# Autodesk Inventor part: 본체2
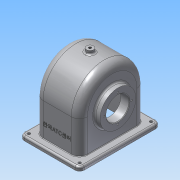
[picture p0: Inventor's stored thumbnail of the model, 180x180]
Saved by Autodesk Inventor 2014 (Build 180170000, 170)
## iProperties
Created: 2016-01
Part Number: 본체2
Material: 알루미늄 6061
Document SubType Name: Modeling
Designer: User
Mass: 842.835 g
Surface Area: 990.698 cm^2
Volume: 311.009 cm^3
Density: 2.71 g/cm^3
Appearance: 알루미늄 - 평지
Author: User
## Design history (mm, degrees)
sketch "스케치1"
  geometry: L1 (-57, 0)-(57, 0); L2 (57, 0)-(57, -64); L3 (57, -64)-(-57, -64); L4 (-57, -64)-(-57, 0); C1 r 57 at (0, 0); 2 further points
  constraints: 8 end point, 2 coincident, 2 parallel, 1 centre point, 1 horizontal, 1 midpoint, 1 perpendicular
  dimensions: "d0" = 114 diameter of C1; "d1" = 114 distance of L2.end L3.end; "d2" = 64 distance of L1.end L2.end
extrude "돌출1" new body sketch "스케치1" stored distance "d3" = 77; taper "d4" = 0 deg
feature "쉘1" dims "d7" = 6
sketch "스케치3"
  geometry: L1 (114, 0)-(114, -77) reference; L2 (0, 0)-(114, 0) reference; L3 (0, 0)-(0, -77) reference; L4 (114, -77)-(0, -77) reference; L5 (-13, 13.5)-(127, 13.5); L6 (127, 13.5)-(127, -90.5); L7 (127, -90.5)-(-13, -90.5); L8 (-13, -90.5)-(-13, 13.5); 3 further points
  constraints: 8 end point, 2 midpoint, 2 parallel, 1 horizontal, 1 horizontal alignment, 1 perpendicular, 1 vertical alignment
  dimensions: "d8" = 140 distance of L5.start L5.end; "d9" = 104 distance of L5.end L6.end
extrude "돌출2" join sketch "스케치3" distance "d10" = 7; taper "d11" = 0 deg
fillet "모깎기1" dims "d12" = 14
node "작업 평면1"
sketch "스케치6"
  geometry: C1 r 6 at (0, 0); 1 further point
  constraints: 1 centre point, 1 coincident
  dimensions: "d36" = 12 diameter of C1
extrude "돌출4" join sketch "스케치6" stored distance "d37" = 10; taper "d38" = 0 deg
hole "구멍2" diameter "d41" = 4.459; stored, may be unused: countersink angle "d45" = 90 deg, drill point angle "d47" = 118 deg; dims "d39" = 10, "d40" = 10, "d42" = 6, "d43" = 4, "d44" = 2, "d46" = 63
fillet "모깎기4" dims "d77" = 8
sketch "스케치9"
  geometry: A1 r 8 centre (119, 82.5) between (127, 82.5) and (119, 90.5) reference; A2 r 8 centre (-5, 82.5) between (-5, 90.5) and (-13, 82.5) reference; A3 r 8 centre (-5, -5.5) between (-13, -5.5) and (-5, -13.5) reference; A4 r 8 centre (119, -5.5) between (119, -13.5) and (127, -5.5) reference; 1 further point
hole "구멍5" sketch "스케치9" at (119, 82.5), (-5, 82.5), (119, -5.5), (-5, -5.5) diameter "d78" = 5; stored, may be unused: countersink angle "d82" = 90 deg, drill point angle "d84" = 118 deg; dims "d79" = 7, "d80" = 4, "d81" = 2, "d83" = 9
fillet "모깎기5" dims "d85" = 3
sketch "스케치10"
  geometry: L1 (49, 0)-(49, -57) reference; L2 (0, 0)-(49, 0) reference; L3 (0, -57)-(0, 0) reference; L4 (-1.387, -30.398)-(50.387, -30.398); L5 (50.387, -30.398)-(50.387, -37.602); L6 (50.387, -37.602)-(-1.387, -37.602); L7 (-1.387, -37.602)-(-1.387, -30.398); L8 (0, -34)-(49, -34); L9 (-19.5, -64)-(68.5, -64) reference; L10 (24.5, 0)-(24.5, -54); L11 (-14, 0)-(-14, -57) reference; L12 (68.5, -57)-(-19.5, -57) reference; 4 further points
  constraints: 4 end point, 4 midpoint, 2 point on line, 1 horizontal alignment, 1 perpendicular, 1 vertical alignment, 2 other
  dimensions: "d86" = 30 distance between parallel lines of L9 L8; "d87" = 38.5 distance between parallel lines of L11 L10
feature "엠보싱1" sketch "스케치10" dims "d8" = 140, "d9" = 104, "d88" = 0.5, "d89" = 0
sketch "스케치11"
  geometry: L1 (-51, -64)-(-51, 0) reference; L2 (51, -64)-(-51, -64) reference; L3 (51, 0)-(51, -64) reference; C1 r 20 at (0, -4) reference; A1 r 51 centre (0, 0) between (51, 0) and (-51, 0) reference
extrude "돌출5" cut sketch "스케치11" distance "d90" = 1; taper "d91" = 0 deg
sketch "스케치12"
  geometry: L1 (-51, -64)-(-51, 0) reference; L2 (51, -64)-(-51, -64) reference; L3 (51, 0)-(51, -64) reference; C1 r 38.908 at (0, -4) reference; A1 r 51 centre (0, 0) between (51, 0) and (-51, 0) reference
extrude "돌출6" cut sketch "스케치12" distance "d92" = 1; taper "d93" = 0 deg
sketch "스케치13"
  geometry: L1 (-4, 43.197)-(-4, -48.942); L2 (-64, -33.5)-(-64, 33.5) reference; L3 (16, 35.5)-(30.899, 35.5); L4 (24, 35.5)-(24, 19.5); L5 (24, 19.5)-(16, 19.5); L6 (16, 19.5)-(16, 35.5); L7 (0, 38.5)-(43, 38.5) reference; L8 (24, 19.5)-(39.943, 38.5); L9 (30.899, 35.5)-(33.416, 38.5); L10 (-4, 33.5)-(16, 33.5); L11 (-4, 38.5)-(33.416, 38.5); L12 (-4, 38.5)-(-4, 33.5); 1 further point
  constraints: 20 end point, 6 point on line, 3 parallel, 2 perpendicular, 1 collinear, 1 horizontal, 1 vertical
  dimensions: "d95" = 60 distance between parallel lines of L1 L2; "d96" = 20 distance between parallel lines of L1 L6; "d99" = 50 deg angle of L8 L5; "d100" = 5 distance between parallel lines of L8 L9; "d102" = 5 distance between parallel lines of L10 L11; "d103" = 56 diameter of L4 L1; "d104" = 19 distance between parallel lines of L11 L5; "d105" = 3 distance between parallel lines of L11 L3
revolve "회전3" stored, may be unused: angle "d106" = 90 deg
revolve "회전4" stored, may be unused: angle "d107" = 90 deg
sketch "스케치14"
  geometry: C1 r 20 at (0, -4) reference; C2 r 31 at (0, -4)
  constraints: 1 centre point, 1 coincident
  dimensions: "d108" = 62 diameter of C2
extrude "돌출7" join sketch "스케치14" distance "d109" = 10; taper "d110" = 0 deg
hole "구멍6" diameter "d113" = 40; stored, may be unused: countersink angle "d117" = 90 deg, drill point angle "d119" = 118 deg; dims "d111" = 10, "d112" = 10, "d114" = 6, "d115" = 4, "d116" = 2, "d118" = 8
chamfer "모따기3" distance "d120" = 1; stored, may be unused: second distance "d121" = 2, angle "d122" = 45 deg
fillet "모깎기6" dims "d123" = 3
sketch "스케치15"
  geometry: C1 r 31 at (0, 0) reference; 2 further points
  constraints: 1 vertical alignment
  dimensions: "d124" = 24 distance of C1.centre point (0, 24)
hole "구멍7" sketch "스케치15" at (0, 24) diameter "d125" = 2.459; stored, may be unused: countersink angle "d129" = 90 deg, drill point angle "d131" = 118 deg; dims "d126" = 6, "d127" = 4, "d128" = 2, "d130" = 8
sketch "스케치16"
  geometry: C1 r 21 at (0, 0) reference; 2 further points
  constraints: 1 vertical alignment
  dimensions: "d135" = 28 distance of C1.centre point (0, 28)
hole "구멍8" sketch "스케치16" at (0, 28) diameter "d136" = 2.459; stored, may be unused: countersink angle "d140" = 90 deg, drill point angle "d142" = 118 deg; dims "d137" = 7, "d138" = 4, "d139" = 2, "d141" = 9
fillet "모깎기7" dims "d146" = 6
fillet "모깎기8" dims "d147" = 3
fillet "모깎기9" dims "d148" = 1
node "솔리드1"
pattern_circular "원형 패턴3" dims angle "d133" = 360 deg
pattern_circular "원형 패턴4" dims angle "d144" = 360 deg
other parameters: "d35" = 63
